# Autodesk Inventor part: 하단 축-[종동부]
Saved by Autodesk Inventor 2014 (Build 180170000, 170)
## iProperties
Created: 2025-02
Part Number: 하단 축-[종동부]
Material: 강철, 탄소
Document SubType Name: Modeling
Designer: dg
Density: 7.87 g/cm^3
Appearance: 반연마
Mass: 53.6272 g
Surface Area: 29.2718 cm^2
Volume: 6.81414 cm^3
Author: jhkim
Creation Date: 2025-01-06
Sending System: Autodesk Inventor 2025
Preprocessor: ST-DEVELOPER v20
Author: dg
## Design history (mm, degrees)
node "하단 축1"
node "솔리드1"
node "기준1"
